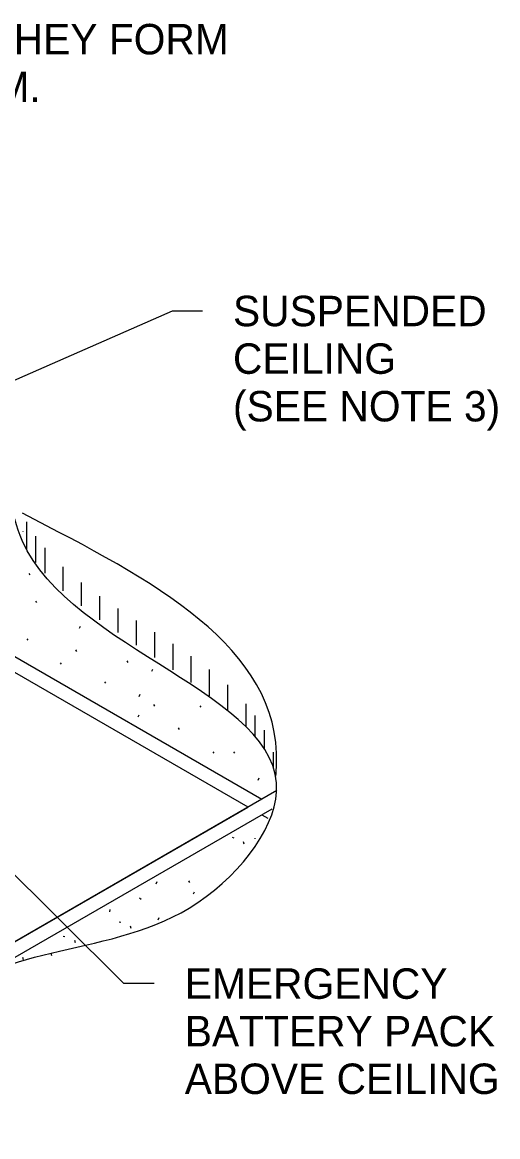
# Model space of a CAD drawing. Extents: x -12092.5 to -12048.3, y -12283.2 to -12205.8.
# Drawn here: x -12060.1 to -12049.7, y -12268.79 to -12244.4 of the extents above; entities that cross this region are included whole.
import ezdxf

# ---------------------------------------------------------------- set-up
doc = ezdxf.new("R2010")
doc.units = 0
for name, color, linetype in [('G-ANNO-TEXT', 7, 'Continuous'), ('G-DETL-LINE', 7, 'Continuous'), ('G-DETL-PATT', 7, 'Continuous')]:
    doc.layers.add(name, color=color, linetype=linetype)

msp = doc.modelspace()

# ---------------------------------------------------------------- linework, layer by layer
at = {"layer": 'G-ANNO-TEXT'}
for p, q in [((-12056.825041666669, -12250.714299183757), (-12061.776083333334, -12252.892184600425)), ((-12056.158375, -12250.714299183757), (-12056.825041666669, -12250.714299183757)), ((-12057.879104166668, -12265.435361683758), (-12062.267291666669, -12261.06653876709)), ((-12057.212437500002, -12265.435361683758), (-12057.879104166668, -12265.435361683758))]:
    msp.add_line(p, q, dxfattribs=at)
at = {"layer": 'G-DETL-LINE'}
for p, q in [((-12055.160395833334, -12261.571020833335), (-12062.580645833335, -12257.286937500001)), ((-12062.28065625, -12257.113739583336), (-12054.860385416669, -12261.397812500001)), ((-12054.534989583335, -12261.209958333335), (-12077.812656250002, -12274.649291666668)), ((-12054.640427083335, -12261.617239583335), (-12077.250458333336, -12274.671156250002)), ((-12063.114843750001, -12266.163520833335), (-12055.160395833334, -12261.571020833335)), ((-12054.860395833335, -12261.744239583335), (-12054.732864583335, -12261.817864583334))]:
    msp.add_line(p, q, dxfattribs=at)
for points in [[(-12065.209760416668, -12249.312927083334), (-12068.289083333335, -12248.770458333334), (-12071.882447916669, -12249.966864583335), (-12073.510843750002, -12250.976395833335), (-12075.660083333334, -12253.249343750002), (-12078.577770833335, -12254.568479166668), (-12080.241072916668, -12256.622104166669), (-12082.416833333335, -12257.298750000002), (-12085.365218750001, -12259.047364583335), (-12087.392239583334, -12262.053750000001), (-12087.392239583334, -12263.004739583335), (-12085.887333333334, -12270.45934375), (-12085.273083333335, -12271.195604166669), (-12082.387489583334, -12274.137000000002), (-12077.473510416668, -12274.658520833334), (-12076.367854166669, -12274.658520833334), (-12074.064416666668, -12273.584802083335), (-12070.747468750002, -12271.314677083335), (-12067.092677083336, -12270.27165625), (-12063.192208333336, -12269.382020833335), (-12061.824302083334, -12266.020250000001), (-12056.450385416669, -12263.782125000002), (-12054.537635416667, -12261.234708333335), (-12060.101572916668, -12255.740187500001), (-12060.917697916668, -12251.902302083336), (-12062.514739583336, -12250.552489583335), (-12064.841333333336, -12249.446656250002), (-12065.182322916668, -12249.321343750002)], [(-12054.553302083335, -12260.898979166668), (-12054.537635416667, -12260.627416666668), (-12060.097718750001, -12255.141083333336)]]:
    msp.add_spline(points, degree=3, dxfattribs=at)
at = {"layer": 'G-DETL-PATT'}
for p, q in [((-12060.002864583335, -12255.925916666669), (-12060.002864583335, -12255.326250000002)), ((-12060.079343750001, -12255.541375), (-12060.079854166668, -12255.534041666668)), ((-12059.802864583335, -12256.216104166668), (-12059.802864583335, -12255.642729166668)), ((-12059.602864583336, -12256.450489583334), (-12059.602864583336, -12255.899614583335)), ((-12059.202864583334, -12256.839052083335), (-12059.202864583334, -12256.3153125)), ((-12059.95782291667, -12256.457708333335), (-12059.936218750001, -12256.490104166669)), ((-12058.802864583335, -12257.170854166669), (-12058.802864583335, -12256.65634375)), ((-12059.807760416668, -12257.065562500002), (-12059.786156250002, -12257.097968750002)), ((-12058.402864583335, -12257.471708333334), (-12058.402864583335, -12256.954937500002)), ((-12058.002864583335, -12257.754437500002), (-12058.002864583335, -12257.228395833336)), ((-12057.602864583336, -12258.027052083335), (-12057.602864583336, -12257.488062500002)), ((-12058.84978125, -12257.658145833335), (-12058.828177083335, -12257.609541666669)), ((-12057.202864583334, -12258.295583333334), (-12057.202864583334, -12257.742791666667)), ((-12059.999489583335, -12257.889937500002), (-12059.977895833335, -12257.922343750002)), ((-12056.802864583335, -12258.565395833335), (-12056.802864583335, -12258.000718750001)), ((-12058.932427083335, -12258.131416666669), (-12058.910833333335, -12258.1638125)), ((-12056.402864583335, -12258.842250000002), (-12056.402864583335, -12258.270687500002)), ((-12059.27422916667, -12258.414531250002), (-12059.252635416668, -12258.446927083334)), ((-12057.815343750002, -12258.372895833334), (-12057.793739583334, -12258.405291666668)), ((-12057.265854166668, -12258.599083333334), (-12057.244260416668, -12258.550479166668)), ((-12056.002864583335, -12259.13359375), (-12056.002864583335, -12258.564166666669)), ((-12058.29885416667, -12258.830875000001), (-12058.277260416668, -12258.863281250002)), ((-12055.602864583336, -12259.450958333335), (-12055.602864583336, -12258.898864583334)), ((-12057.540958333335, -12259.148656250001), (-12057.519354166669, -12259.100052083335)), ((-12057.231791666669, -12259.330489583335), (-12057.21019791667, -12259.362895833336)), ((-12056.214739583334, -12259.355468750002), (-12056.193145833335, -12259.387864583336)), ((-12055.202864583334, -12259.817041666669), (-12055.202864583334, -12259.308812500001)), ((-12057.565968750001, -12259.598302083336), (-12057.544364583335, -12259.549708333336)), ((-12055.002864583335, -12260.034500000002), (-12055.002864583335, -12259.565302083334)), ((-12056.689927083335, -12259.838427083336), (-12056.668333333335, -12259.870833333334)), ((-12054.802864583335, -12260.298916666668), (-12054.802864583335, -12259.888427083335)), ((-12055.931302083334, -12260.36303125), (-12055.909708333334, -12260.395427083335)), ((-12055.481145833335, -12260.36303125), (-12055.459541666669, -12260.395427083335)), ((-12054.602864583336, -12260.691604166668), (-12054.602864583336, -12260.368031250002)), ((-12054.939979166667, -12260.980583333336), (-12054.918385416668, -12260.931979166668)), ((-12055.512447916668, -12262.234083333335), (-12055.475072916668, -12262.245020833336)), ((-12055.247427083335, -12262.383833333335), (-12055.262083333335, -12262.332770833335)), ((-12055.002864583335, -12262.265416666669), (-12055.002864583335, -12262.253031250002)), ((-12056.460895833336, -12263.18829166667), (-12056.439291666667, -12263.220687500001)), ((-12057.174114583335, -12263.252145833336), (-12057.152552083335, -12263.203614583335)), ((-12056.354145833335, -12263.473354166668), (-12056.332541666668, -12263.424833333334)), ((-12057.533604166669, -12263.561739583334), (-12057.502218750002, -12263.584802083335)), ((-12058.181979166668, -12263.865677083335), (-12058.178302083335, -12263.812708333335)), ((-12057.982468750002, -12264.080906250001), (-12057.945093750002, -12264.091843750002)), ((-12057.125135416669, -12264.036677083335), (-12057.10353125, -12263.988156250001)), ((-12059.203197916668, -12264.394645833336), (-12059.165822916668, -12264.405583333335)), ((-12057.717458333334, -12264.230656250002), (-12057.732104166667, -12264.179593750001)), ((-12058.938177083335, -12264.544395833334), (-12058.952833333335, -12264.493333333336)), ((-12060.075583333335, -12264.913031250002), (-12060.090239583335, -12264.861989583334)), ((-12059.452166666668, -12264.829614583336), (-12059.46682291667, -12264.778552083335))]:
    msp.add_line(p, q, dxfattribs=at)

# ---------------------------------------------------------------- texts
at = {"layer": 'G-ANNO-TEXT'}
for s, p in [('LOCATE REMOTE TEST/MONITOR MODULES IDENTICALLY SO THAT THEY FORM', (-12090.452958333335, -12245.097218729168)), ('A STRAIGHT LINE WHEN VIEWED FROM END OF CORRIDOR OR ROOM.', (-12090.452958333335, -12246.138885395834)), ('SUSPENDED', (-12055.491708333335, -12251.047624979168)), ('CEILING', (-12055.491708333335, -12252.089291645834)), ('(SEE NOTE 3)', (-12055.491708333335, -12253.1309583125)), ('EMERGENCY', (-12056.545770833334, -12265.768687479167)), ('BATTERY PACK', (-12056.545770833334, -12266.810354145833)), ('ABOVE CEILING', (-12056.545770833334, -12267.852020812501))]:
    msp.add_text(s, height=0.6666666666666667, dxfattribs=at).set_placement(p)

doc.saveas('drawing.dxf')
